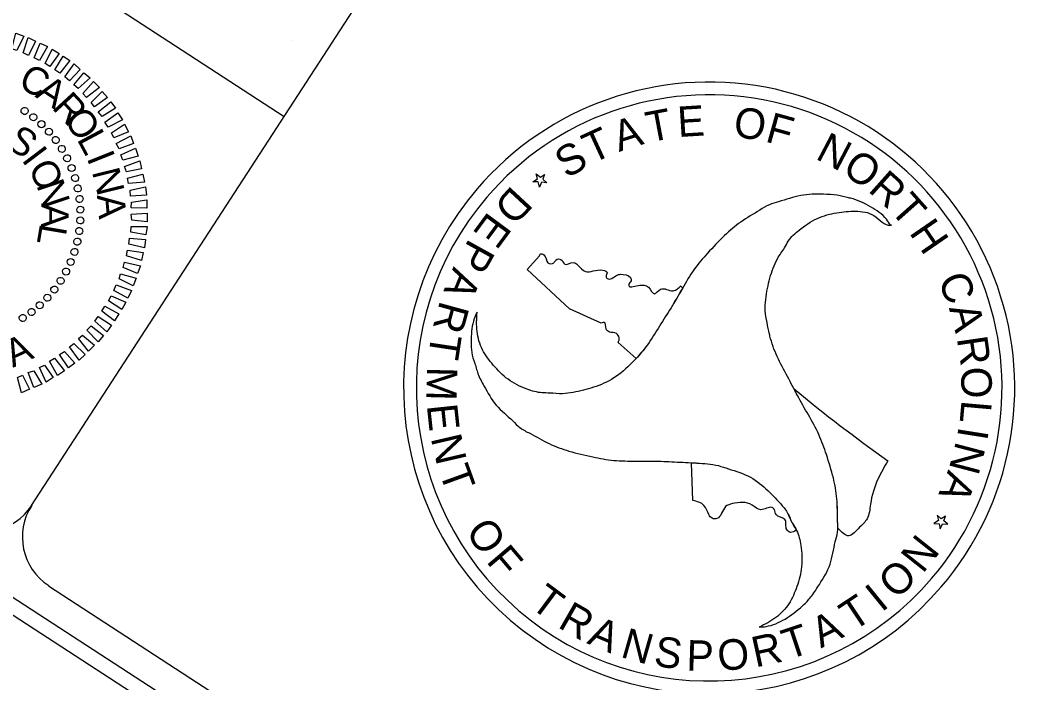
# Model space of a CAD drawing. Extents: x 2291197 to 2302790, y 592892 to 604246.
# Drawn here: x 2298859 to 2299556, y 597328 to 597785 of the extents above; entities that cross this region are included whole.
import ezdxf

# ---------------------------------------------------------------- set-up
doc = ezdxf.new("R2010")
doc.units = 0
for name, color, linetype in [('Default', 7, 'Continuous'), ('Old_Level_2', 7, 'Continuous'), ('Sheet Plot Border Inside CELL', 7, 'Continuous'), ('Sheet Professional Seal CELL', 7, 'Continuous'), ('Sheet Title CELL', 7, 'Continuous')]:
    doc.layers.add(name, color=color, linetype=linetype)

# ---------------------------------------------------------------- blocks, each defined once
blk = doc.blocks.new('POINT_DISPLAY')
at = {"layer": 'Default'}
blk.add_line((0, 0), (0, 0), dxfattribs=at)

msp = doc.modelspace()

# ---------------------------------------------------------------- linework, layer by layer
at = {"layer": 'Old_Level_2'}
msp.add_line((2299047.07, 597770.56), (2299047.07, 597770.56), dxfattribs=at)
at = {"layer": 'Sheet Plot Border Inside CELL'}
msp.add_lwpolyline([(2293886.07, 600604.03), (2299474.98, 596970.9), (2301775.2, 600509.37), (2296186.29, 604142.5)], close=True, dxfattribs=at)
at = {"layer": 'Sheet Professional Seal CELL'}
for points in [[(2298853.37, 597764.89), (2298856.05, 597775.83), (2298861.51, 597773.69), (2298856.8, 597763.67)], [(2298861.27, 597762.17), (2298864.66, 597772.65), (2298869.7, 597770.18), (2298864.94, 597760.39)], [(2298868.7, 597758.75), (2298872.8, 597768.76), (2298877.93, 597766.44), (2298872.38, 597756.96)], [(2298876.24, 597754.86), (2298881.23, 597764.7), (2298885.9, 597761.66), (2298879.64, 597752.65)], [(2298883.04, 597750.44), (2298888.73, 597759.82), (2298893.4, 597756.79), (2298886.43, 597748.23)], [(2298889.93, 597745.56), (2298896.33, 597754.48), (2298900.54, 597750.74), (2298893.05, 597742.93)], [(2298896.07, 597740.15), (2298903.09, 597748.47), (2298907.39, 597744.87), (2298899.19, 597737.52)], [(2298902.37, 597734.04), (2298909.62, 597742.41), (2298913.79, 597738.3), (2298904.88, 597731.4)], [(2298908.06, 597727.93), (2298915.74, 597735.42), (2298919.3, 597731.29), (2298910.39, 597725)], [(2298912.86, 597721.38), (2298921.77, 597728.28), (2298924.77, 597723.91), (2298915.62, 597718.19)], [(2298917.63, 597714.46), (2298926.54, 597720.75), (2298929.64, 597715.91), (2298919.82, 597711.02)], [(2298922.11, 597707.12), (2298931.13, 597712.93), (2298933.95, 597707.68), (2298923.69, 597703.67)], [(2298925.38, 597699.76), (2298935.53, 597704.84), (2298937.36, 597699.62), (2298927.39, 597696.04)], [(2298928.51, 597691.88), (2298938.67, 597696.36), (2298940.56, 597690.9), (2298929.91, 597688.15)], [(2298931.18, 597683.91), (2298941.72, 597687.73), (2298942.91, 597682.13), (2298932.58, 597680.18)], [(2298933.15, 597675.79), (2298943.65, 597678.62), (2298944.84, 597673.02), (2298933.94, 597672.05)], [(2298934.93, 597667.38), (2298945.53, 597669.75), (2298946.25, 597664.05), (2298935.17, 597663.4)], [(2298935.82, 597659.15), (2298946.57, 597660.82), (2298946.59, 597654.97), (2298935.77, 597655.36)], [(2298935.73, 597650.96), (2298946.82, 597651.6), (2298946.84, 597645.75), (2298936.1, 597646.89)], [(2298935.6, 597642.39), (2298946.69, 597642.42), (2298945.82, 597636.75), (2298935.54, 597638.6)], [(2298934.61, 597634.38), (2298945.67, 597633.43), (2298944.8, 597627.75), (2298934, 597630.34)], [(2298933.07, 597626.11), (2298944.04, 597624.42), (2298942.89, 597618.93), (2298932.55, 597622.22)], [(2298931.06, 597617.76), (2298942.18, 597615.36), (2298940.13, 597610.05), (2298930.12, 597614.15)], [(2298928.34, 597609.87), (2298939.09, 597606.9), (2298936.96, 597601.44), (2298927.4, 597606.24)], [(2298925.34, 597602.15), (2298935.92, 597598.3), (2298933.36, 597593.11), (2298923.84, 597598.3)], [(2298921.91, 597594.71), (2298932.03, 597590.15), (2298929.19, 597585.15), (2298919.99, 597591.13)], [(2298917.6, 597587.45), (2298927.26, 597582.18), (2298924.13, 597577.37), (2298915.39, 597584.06)], [(2298913, 597580.38), (2298922.2, 597574.4), (2298918.79, 597569.77), (2298910.51, 597577.17)], [(2298902.19, 597567.47), (2298910.47, 597560.69), (2298906.34, 597556.52), (2298899.27, 597565.14)], [(2298908.02, 597573.95), (2298916.62, 597567.36), (2298912.92, 597562.92), (2298905.1, 597571.02)], [(2298896.08, 597561.79), (2298903.89, 597554.29), (2298899.87, 597550.27), (2298893.15, 597559.46)], [(2298889.69, 597556.28), (2298896.89, 597548.17), (2298892.35, 597544.88), (2298886.34, 597554.23)], [(2298875.93, 597546.9), (2298881.79, 597538.26), (2298876.96, 597535.16), (2298872.49, 597545.31)], [(2298882.85, 597551.66), (2298889.61, 597542.84), (2298884.77, 597539.74), (2298879.42, 597549.47)], [(2298860.71, 597539.89), (2298865.45, 597530.16), (2298860.1, 597527.8), (2298857.26, 597538.3)], [(2298868.59, 597543.02), (2298873.98, 597533.67), (2298868.63, 597531.32), (2298864.71, 597541.71)]]:
    msp.add_lwpolyline(points, close=True, dxfattribs=at)
for centre, major_axis in [((2298862.16, 597722.09), (1.32, 2.04)), ((2298868.17, 597717.8), (1.5, 1.91)), ((2298873.79, 597713), (1.66, 1.78)), ((2298878.96, 597707.73), (1.81, 1.63)), ((2298883.66, 597702.02), (1.94, 1.46)), ((2298887.84, 597695.94), (2.06, 1.29)), ((2298891.47, 597689.51), (2.17, 1.1)), ((2298894.53, 597682.78), (2.25, 0.91)), ((2298896.99, 597675.82), (2.32, 0.71)), ((2298898.84, 597668.67), (2.38, 0.5)), ((2298900.06, 597661.38), (2.41, 0.3)), ((2298900.63, 597654.02), (2.43, 0.08)), ((2298900.57, 597646.64), (2.43, -0.13)), ((2298899.85, 597639.28), (2.41, -0.34)), ((2298898.5, 597632.02), (2.37, -0.55)), ((2298896.53, 597624.91), (2.31, -0.75)), ((2298893.94, 597617.99), (2.24, -0.95)), ((2298890.76, 597611.33), (2.15, -1.14)), ((2298887, 597604.96), (2.04, -1.32)), ((2298877.91, 597593.34), (1.78, -1.66)), ((2298882.71, 597598.95), (1.91, -1.5)), ((2298872.64, 597588.16), (1.63, -1.81)), ((2298860.85, 597579.29), (1.29, -2.06)), ((2298866.94, 597583.47), (1.46, -1.94))]:
    msp.add_ellipse(centre, major_axis=major_axis, ratio=0.999708, dxfattribs=at)
at = {"layer": 'Sheet Title CELL'}
for p, q in [((2298301.32, 598199.42), (2299041.37, 597718.34)), ((2298866.91, 597449.97), (2299215.73, 597986.56)), ((2299216.05, 597675.28), (2299215.25, 597678.85)), ((2299215.25, 597678.85), (2299218.05, 597676.45)), ((2299212.97, 597673.31), (2299216.05, 597675.28)), ((2299216.53, 597673.14), (2299212.97, 597673.31)), ((2299217.38, 597669.53), (2299216.53, 597673.14)), ((2299218.81, 597672.92), (2299217.38, 597669.53)), ((2299218.05, 597676.45), (2299221, 597678.36)), ((2299222.51, 597672.63), (2299218.81, 597672.92)), ((2299221, 597678.36), (2299219.76, 597674.98)), ((2299219.76, 597674.98), (2299222.51, 597672.63)), ((2299460.25, 597643.43), (2299459.68, 597643.34)), ((2299460.25, 597643.43), (2299459.68, 597643.34)), ((2299208.84, 597612.8), (2299217.43, 597622.15)), ((2299238.24, 597585.63), (2299208.84, 597612.8)), ((2299260.04, 597575.82), (2299238.24, 597585.63)), ((2299284.26, 597551.36), (2299271.72, 597562.36)), ((2299393.09, 597530.42), (2299393.09, 597530.42)), ((2299323.21, 597453.51), (2299322.27, 597479.59)), ((2299322.27, 597479.59), (2299322.27, 597479.59)), ((2299494.6, 597440.93), (2299491.85, 597443.29)), ((2299491.85, 597443.29), (2299492.75, 597439.73)), ((2299497.65, 597442.76), (2299494.6, 597440.93)), ((2299496.41, 597439.39), (2299497.65, 597442.76)), ((2299492.75, 597439.73), (2299489.66, 597437.76)), ((2299489.66, 597437.76), (2299493.18, 597437.54)), ((2299493.18, 597437.54), (2299494.03, 597434.02)), ((2299494.03, 597434.02), (2299495.5, 597437.37)), ((2299495.5, 597437.37), (2299499.19, 597437.16)), ((2299499.19, 597437.16), (2299496.41, 597439.39)), ((2299494.67, 597393.95), (2299494.67, 597393.95))]:
    msp.add_line(p, q, dxfattribs=at)
for points in [[(2294441.63, 600255.04), (2299405.08, 597028.5)], [(2298878.66, 597394.62), (2299399.24, 597056.21)]]:
    msp.add_lwpolyline(points, dxfattribs=at)
for centre, radius, start, end in [((2299334.56, 597531.15), 210.87, 319.39483, 139.39483), ((2299334.56, 597531.15), 202.08, 319.39483, 139.39483), ((2299334.56, 597531.15), 210.87, 139.39483, 319.39483), ((2299334.56, 597531.15), 202.08, 139.39483, 319.39483), ((2300100.08, 598388.47), 1111.78, 225.07332, 225.17292), ((2300100.08, 598388.47), 1111.78, 230.51238, 234.71839), ((2298833.52, 597471.95), 40, 236.9737, 326.9737), ((2298900.59, 597428.35), 40, 146.9737, 236.9737)]:
    msp.add_arc(centre, radius, start, end, dxfattribs=at)
for points in [[(2299459.68, 597643.34), (2299456.89, 597647.38), (2299445.89, 597656.06), (2299432.1, 597661.87), (2299430.71, 597662.16), (2299422.86, 597663.96), (2299413.45, 597664.61), (2299397.73, 597663.84), (2299382.42, 597659.43), (2299376.07, 597657.39), (2299369.56, 597653.74), (2299356.32, 597645.5), (2299345.12, 597636.17), (2299333.46, 597624.02), (2299324.05, 597612.66), (2299316.1, 597599.64), (2299308.21, 597586.4), (2299300.27, 597573.77), (2299291.95, 597560.9), (2299282.2, 597549.43), (2299281.29, 597548.47), (2299268.8, 597538.02), (2299254.71, 597531.58), (2299240.67, 597528.06), (2299233.38, 597527.15), (2299224.44, 597527.57), (2299219.33, 597527.75), (2299208.89, 597530.27), (2299195.73, 597537.11), (2299185.54, 597546.92), (2299178.12, 597557.47), (2299174.37, 597569.99), (2299174.36, 597583.33)], [(2299369.15, 597366.22), (2299373.81, 597366.67), (2299386.93, 597371.8), (2299398.87, 597380.83), (2299399.95, 597381.8), (2299405.29, 597387.84), (2299410.63, 597395.69), (2299417.94, 597409.6), (2299421.58, 597425.08), (2299423.12, 597431.58), (2299423.2, 597439.17), (2299422.67, 597454.69), (2299420.24, 597469.04), (2299415.45, 597485.16), (2299410.23, 597498.94), (2299403.02, 597512.53), (2299395.53, 597525.87), (2299388.63, 597538.94), (2299381.49, 597552.8), (2299376.51, 597566.87), (2299376.23, 597568.18), (2299373.3, 597584.35), (2299374.82, 597599.76), (2299378.67, 597613.66), (2299381.67, 597620.23), (2299386.54, 597627.83), (2299389.16, 597632.33), (2299396.65, 597639.91), (2299409.19, 597648.01), (2299422.63, 597651.88), (2299435.49, 597652.96), (2299448.27, 597649.91), (2299459.68, 597643.34), (2299460.25, 597643.43)], [(2299217.43, 597622.15), (2299217.87, 597623.34), (2299220.38, 597623), (2299223.3, 597617.28), (2299227.25, 597617.27), (2299228.82, 597619.3), (2299232.29, 597619.7), (2299234.85, 597616.44), (2299240.7, 597617.6), (2299243.79, 597616.02), (2299249.2, 597611.38), (2299261.14, 597612.34), (2299264.17, 597610.4), (2299263.37, 597608.13), (2299264.74, 597606.37), (2299272.05, 597609.33), (2299273.41, 597609.48), (2299280.15, 597607.16), (2299280.67, 597605.07), (2299279.01, 597602.37), (2299279.32, 597601.29), (2299282, 597601.05), (2299286.67, 597601.98), (2299292.63, 597600.58), (2299296.83, 597595.98), (2299300.94, 597599.14), (2299309.61, 597598.12), (2299312.66, 597599.37), (2299314.9, 597601.41)], [(2299316.3, 597599.96), (2299316.1, 597599.64), (2299308.21, 597586.4), (2299300.27, 597573.77), (2299291.95, 597560.9), (2299284.22, 597551.4)], [(2299174.36, 597583.33), (2299172.41, 597578.75), (2299170.33, 597564.9), (2299172.09, 597550.05), (2299172.58, 597548.8), (2299174.96, 597540.92), (2299179.15, 597532.55), (2299187.63, 597519.2), (2299199.09, 597508.38), (2299203.97, 597503.79), (2299210.7, 597499.83), (2299224.19, 597492.71), (2299237.75, 597487.59), (2299254.23, 597483.58), (2299268.65, 597481.19), (2299284.06, 597480.73), (2299299.45, 597480.63), (2299314.35, 597479.96), (2299329.66, 597479.1), (2299344.49, 597476.51), (2299345.95, 597476), (2299361.27, 597470.44), (2299373.74, 597461.56), (2299383.75, 597451.34), (2299388.38, 597445.31), (2299392.18, 597437.36), (2299394.92, 597432.78), (2299397.75, 597422.54), (2299398.35, 597407.78), (2299395.06, 597394.14), (2299389.54, 597382.33), (2299380.56, 597372.82), (2299369.15, 597366.22)], [(2299271.72, 597562.36), (2299272.48, 597565.74), (2299270.62, 597568.57), (2299265.79, 597569.66), (2299263.4, 597571.96), (2299262.36, 597576.31), (2299260.04, 597575.82)], [(2299423.4, 597434.31), (2299423.2, 597439.17), (2299422.67, 597454.69), (2299420.24, 597469.04), (2299415.45, 597485.16), (2299410.23, 597498.94), (2299403.02, 597512.53), (2299395.53, 597525.87), (2299393.09, 597530.42)], [(2299322.27, 597479.59), (2299329.66, 597479.1), (2299344.49, 597476.51), (2299345.95, 597476), (2299361.27, 597470.44), (2299373.74, 597461.56), (2299383.75, 597451.34), (2299388.38, 597445.31), (2299392.18, 597437.36), (2299394.68, 597433.08)], [(2299457.89, 597480.88), (2299451.02, 597468.25), (2299445.84, 597450.88), (2299443.54, 597440.91), (2299438.36, 597435.06), (2299430.93, 597429.17), (2299423.48, 597434.31)], [(2299394.59, 597433.07), (2299390.72, 597431.53), (2299388.14, 597433.41), (2299386.8, 597440.4), (2299380.74, 597443.79), (2299379.54, 597447.2), (2299378.02, 597448.59), (2299370.24, 597447.11), (2299364.14, 597450.36), (2299350.59, 597451.36), (2299345.83, 597449.27), (2299339.86, 597441.05), (2299336.52, 597441.28), (2299334.37, 597443.78), (2299330.96, 597450.16), (2299323.21, 597453.51)]]:
    msp.add_spline(points, degree=3, dxfattribs=at)

# ---------------------------------------------------------------- block references
at = {"layer": 'Sheet Professional Seal CELL', "xscale": 207.0597976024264, "yscale": 207.05979760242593, "rotation": -33.025869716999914}
for p in [(2298862.2, 597722.1), (2298868.24, 597717.78), (2298873.78, 597712.97), (2298879.04, 597707.74), (2298883.78, 597702.04), (2298887.88, 597695.96), (2298891.56, 597689.54), (2298894.58, 597682.74), (2298897.15, 597675.84), (2298898.92, 597668.65), (2298900.22, 597661.36), (2298900.68, 597654.02), (2298900.67, 597646.57), (2298899.91, 597639.21), (2298898.64, 597631.99), (2298896.62, 597624.85), (2298890.83, 597611.3), (2298887.06, 597604.89), (2298882.73, 597598.85), (2298877.92, 597593.32), (2298867, 597583.31), (2298872.7, 597588.06), (2298860.91, 597579.21)]:
    msp.add_blockref('POINT_DISPLAY', p, dxfattribs=at)

# ---------------------------------------------------------------- texts
at = {"layer": 'Sheet Professional Seal CELL'}
for s, rotation, p in [('C', 334.194, (2298856.94, 597738.42)), ('A', 326.99445, (2298868.77, 597732.13)), ('R', 312.59523, (2298880.45, 597724.12)), ('O', 305.39529, (2298888.65, 597715.96)), ('S', 325.87453, (2298848.53, 597697.98)), ('L', 298.19501, (2298897.93, 597702.68)), ('I', 307.16373, (2298859.61, 597688.35)), ('I', 291.7547, (2298904.79, 597689.83)), ('O', 297.80761, (2298864.13, 597682.57)), ('N', 283.79304, (2298908.52, 597680.3)), ('N', 288.45074, (2298870.1, 597671.06)), ('A', 269.7344, (2298873.61, 597658.48)), ('A', 275.03625, (2298912.06, 597663.95)), ('L', 260.37498, (2298872.92, 597645.04)), ('A', 24.85242, (2298854.04, 597544.92))]:
    msp.add_text(s, height=19.03, rotation=rotation, dxfattribs=at).set_placement(p)
at = {"layer": 'Sheet Title CELL'}
for s, height, rotation, p in [('T', 20.98, 10.6674, (2299293.03, 597700.34)), ('E', 20.96, 3.55177, (2299313.26, 597704.07)), ('O', 21.05, 351.61239, (2299350.55, 597704.54)), ('F', 21.07, 344.46555, (2299372.52, 597701.18)), ('A', 21.1, 17.72262, (2299272.3, 597693.74)), ('T', 21.07, 24.77493, (2299253.53, 597685.38)), ('N', 21.03, 332.37861, (2299407.2, 597689.48)), ('S', 21.01, 31.15108, (2299236.37, 597675.07)), ('O', 21.08, 324.8805, (2299425.36, 597679.84)), ('R', 21.03, 318.27057, (2299443.54, 597667.05)), ('D', 21.03, 227.24783, (2299198.54, 597671.27)), ('T', 21.08, 311.62094, (2299458.57, 597653.67)), ('E', 20.94, 233.53572, (2299182.32, 597653.4)), ('H', 21, 304.53622, (2299472.13, 597638.18)), ('P', 21.03, 241.06811, (2299169.08, 597634.79)), ('A', 21, 247.66069, (2299158.22, 597615.12)), ('C', 20.97, 292.19387, (2299492.09, 597605.76)), ('R', 21.02, 254.72932, (2299149.01, 597591.98)), ('A', 21.01, 284.69684, (2299499.92, 597586.28)), ('T', 21.01, 261.37986, (2299143.11, 597569.54)), ('R', 21, 278.33289, (2299505.42, 597565.43)), ('M', 20.97, 268.6149, (2299139.88, 597545.89)), ('O', 21.06, 271.21329, (2299508.28, 597545.53)), ('E', 20.97, 276.08167, (2299139.67, 597519.15)), ('L', 20.97, 264.97961, (2299508.76, 597523.13)), ('N', 21.07, 283.05321, (2299142.33, 597496.61)), ('I', 21.06, 260.99027, (2299506.78, 597505.08)), ('N', 21.02, 255.29017, (2299505.03, 597494.97)), ('T', 20.99, 289.89521, (2299147.92, 597473.55)), ('A', 21.03, 247.85819, (2299499.65, 597475.05)), ('O', 21.01, 303.1989, (2299165.97, 597432.47)), ('N', 21.03, 51.60296, (2299481.9, 597402.59)), ('F', 21, 310.36413, (2299180.17, 597411.4)), ('O', 20.95, 44.35495, (2299463.91, 597384.67)), ('T', 20.96, 323.27336, (2299210.08, 597380.5)), ('I', 21.08, 39.21932, (2299453.54, 597376.03)), ('T', 21, 33.56941, (2299433.81, 597362.81)), ('R', 21.04, 330.22998, (2299229.33, 597366.47)), ('A', 21.07, 26.48499, (2299411.64, 597351.45)), ('A', 20.96, 336.98311, (2299249.65, 597355.22)), ('N', 20.96, 344.01474, (2299272.66, 597345.86)), ('T', 20.96, 18.39795, (2299389.15, 597343.56)), ('S', 20.94, 351.22521, (2299295.65, 597339.74)), ('O', 21.07, 5.10905, (2299341.16, 597335.88)), ('R', 21.06, 12.29816, (2299366.46, 597338.31)), ('P', 21.02, 358.41706, (2299318.65, 597336.32))]:
    msp.add_text(s, height=height, rotation=rotation, dxfattribs=at).set_placement(p)

doc.saveas('drawing.dxf')
